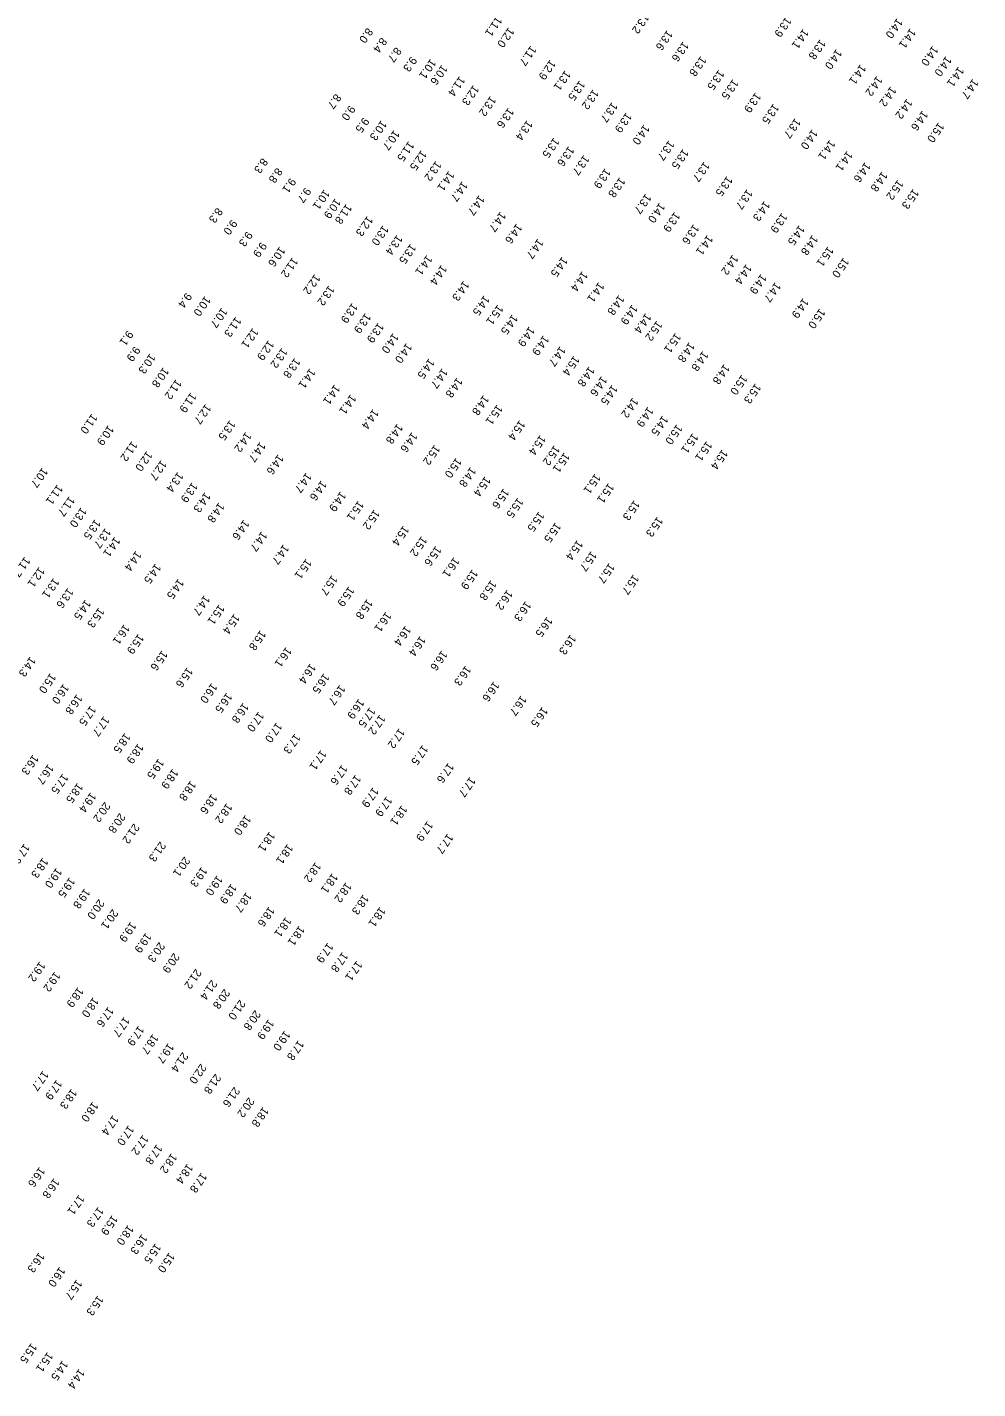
# Model space of a CAD drawing. Extents: x 815385 to 820851, y 582449 to 604245.
# Drawn here: x 817174 to 817768, y 584611 to 585462 of the extents above; entities that cross this region are included whole.
import ezdxf

# ---------------------------------------------------------------- set-up
doc = ezdxf.new("R2010")
doc.units = 0
doc.layers.add('V-TOPO-SOUN-021509', color=7, linetype='Continuous')
doc.layers.add('V-TOPO-SOUN-101408', color=7, linetype='Continuous')

msp = doc.modelspace()

# ---------------------------------------------------------------- texts
at = {"layer": 'V-TOPO-SOUN-021509'}
for s, p in [('13.9 ', (817647.89, 585468.39)), ('14.1 ', (817658.74, 585461.03)), ('14.0 ', (817717.43, 585467.62)), ('14.1 ', (817725.65, 585461.3)), ('13.8 ', (817669.26, 585454.39)), ('14.0 ', (817679.45, 585448.29)), ('14.0 ', (817739.62, 585450.38)), ('14.0 ', (817747.96, 585443.94)), ('14.1 ', (817694.46, 585438.8)), ('14.1 ', (817755.74, 585437.32)), ('14.2 ', (817704.76, 585431.54)), ('14.7 ', (817764.78, 585429.81)), ('14.2 ', (817713.42, 585425.04)), ('14.2 ', (817723.51, 585417.31)), ('14.6 ', (817733.27, 585409.94)), ('15.0 ', (817743.37, 585402.56))]:
    msp.add_text(s, height=5, rotation=234.911, dxfattribs=at).set_placement(p)
at = {"layer": 'V-TOPO-SOUN-101408'}
for s, p in [('11.1 ', (817467.09, 585468.75)), ('13.2 ', (817558.89, 585470.52)), ('8.0', (817386.22, 585461.66)), ('12.0 ', (817474.61, 585461.92)), ('13.6 ', (817573.71, 585460.17)), ('8.4', (817394.98, 585455.6)), ('13.6 ', (817583.69, 585453.06)), ('8.7', (817404.07, 585449.57)), ('9.3', (817413.72, 585443.74)), ('11.7 ', (817488.44, 585450.47)), ('13.8 ', (817594.69, 585443.92)), ('10.1 ', (817425.81, 585442.21)), ('10.6 ', (817432.9, 585438.55)), ('12.9 ', (817500.54, 585441.67)), ('13.1 ', (817509.9, 585435.01)), ('13.5 ', (817605.9, 585435.35)), ('11.4 ', (817443.93, 585431.4)), ('12.3 ', (817452.6, 585425.82)), ('13.5 ', (817518.93, 585428.7)), ('13.5 ', (817614.78, 585429.54)), ('8.7', (817366.39, 585420.47)), ('13.2 ', (817463.24, 585418.98)), ('13.2 ', (817527.45, 585423.19)), ('13.9 ', (817628.91, 585421.18)), ('9.0', (817375.21, 585413.29)), ('13.6 ', (817474.41, 585411.64)), ('13.7 ', (817539.21, 585415.12)), ('13.5 ', (817640.12, 585414.21)), ('9.5', (817383.89, 585405.67)), ('10.3 ', (817395.01, 585403.85)), ('13.4 ', (817486.11, 585403.89)), ('13.9 ', (817548.13, 585408.69)), ('14.0 ', (817559.21, 585401.14)), ('13.7 ', (817653.7, 585405.17)), ('10.7 ', (817402.98, 585397.75)), ('13.5 ', (817502.84, 585392.98)), ('14.0 ', (817664.37, 585398.23)), ('11.5 ', (817412.1, 585390.73)), ('12.5 ', (817420, 585385.11)), ('13.6 ', (817512.12, 585387.62)), ('13.7 ', (817574.72, 585391.31)), ('13.5 ', (817583.63, 585385.96)), ('14.1 ', (817675.29, 585391.64)), ('14.1 ', (817686.17, 585384.68)), ('8.3', (817320.57, 585380.34)), ('13.2 ', (817429.12, 585378.47)), ('13.7 ', (817521.59, 585382.11)), ('13.7 ', (817596.8, 585377.98)), ('14.6 ', (817697.42, 585377.68)), ('8.8', (817329.68, 585374.22)), ('9.1', (817338.15, 585367.91)), ('14.1 ', (817437.2, 585372.19)), ('13.9 ', (817534.92, 585373.86)), ('13.8 ', (817544.02, 585368.2)), ('13.5 ', (817611.1, 585368.98)), ('14.8 ', (817708, 585371.83)), ('15.2 ', (817717.86, 585366.7)), ('9.7', (817347.55, 585361.91)), ('10.1 ', (817359.33, 585360.6)), ('14.7 ', (817445.58, 585365.68)), ('13.7 ', (817560.25, 585357.96)), ('13.7 ', (817623.63, 585360.75)), ('15.3 ', (817727.54, 585361.02)), ('10.9 ', (817366.24, 585355.06)), ('11.8 ', (817373.17, 585351.6)), ('14.7 ', (817456.13, 585357.03)), ('14.0 ', (817568.91, 585352.33)), ('14.3 ', (817634.46, 585353.43)), ('8.3', (817292.28, 585349.31)), ('9.0', (817301.4, 585341.82)), ('12.3 ', (817386.31, 585344.05)), ('14.7 ', (817469.41, 585346.73)), ('13.9 ', (817578.34, 585346.61)), ('13.9 ', (817645.39, 585346.03)), ('9.3', (817310.99, 585334.51)), ('13.0 ', (817396.09, 585338.22)), ('13.4 ', (817404.85, 585332.24)), ('14.6 ', (817479.59, 585339.35)), ('13.6 ', (817590.22, 585338.89)), ('14.1 ', (817598.83, 585332.19)), ('14.5 ', (817656.27, 585338.37)), ('9.9', (817319.85, 585327.81)), ('10.6 ', (817331.48, 585324.94)), ('13.5 ', (817413.3, 585326.74)), ('14.7 ', (817492.84, 585329.89)), ('14.8 ', (817664.48, 585332.13)), ('15.1 ', (817674.21, 585325.04)), ('11.2 ', (817339.52, 585318.22)), ('14.1 ', (817423.45, 585319.63)), ('14.5 ', (817508.04, 585318.56)), ('14.2 ', (817614.64, 585319.86)), ('15.0 ', (817683.93, 585318.07)), ('12.2 ', (817353.38, 585307.72)), ('14.4 ', (817432.59, 585313.52)), ('14.4 ', (817520.64, 585309.57)), ('14.4 ', (817623.12, 585313.99)), ('14.9 ', (817632.4, 585307.87)), ('13.2 ', (817362.26, 585300.69)), ('14.3 ', (817446.47, 585303.59)), ('14.1 ', (817530.91, 585302.71)), ('14.7 ', (817641.28, 585302.74)), ('9.4', (817273.05, 585296.22)), ('10.0 ', (817284.86, 585294.08)), ('13.9 ', (817376.86, 585289.72)), ('14.5 ', (817459.27, 585294.46)), ('14.8 ', (817543.51, 585294.7)), ('14.9 ', (817658.69, 585292.77)), ('10.7 ', (817295.31, 585286.78)), ('13.9 ', (817385.04, 585283.36)), ('15.1 ', (817467.77, 585288.61)), ('14.5 ', (817476.89, 585282.58)), ('14.9 ', (817551.78, 585288.71)), ('14.4 ', (817560.25, 585283.32)), ('15.0 ', (817669.01, 585286.28)), ('11.3 ', (817304.02, 585281.05)), ('12.1 ', (817314.7, 585274.09)), ('13.9 ', (817393.14, 585277.42)), ('14.9 ', (817487.48, 585275.01)), ('15.2 ', (817567.2, 585278.62)), ('9.1', (817236.43, 585272.58)), ('12.9 ', (817324.5, 585266.45)), ('14.0 ', (817402.4, 585270.88)), ('14.0 ', (817410.76, 585264.69)), ('14.9 ', (817496.38, 585269.53)), ('15.1 ', (817578.91, 585271.01)), ('14.8 ', (817587.5, 585265.21)), ('9.9', (817240.81, 585262.73)), ('10.3 ', (817250.4, 585258.1)), ('13.2 ', (817332.9, 585261.65)), ('14.7 ', (817506.77, 585262.71)), ('15.4 ', (817515.44, 585256.81)), ('14.8 ', (817595.99, 585259.72)), ('10.8 ', (817258.78, 585249.5)), ('13.8 ', (817340.89, 585255.37)), ('14.1 ', (817350.36, 585248.88)), ('14.5 ', (817424.79, 585255.03)), ('14.7 ', (817433.1, 585248.9)), ('14.8 ', (817524.88, 585250.04)), ('14.8 ', (817609.32, 585251.51)), ('11.2 ', (817266.74, 585242.04)), ('14.1 ', (817365.79, 585238.75)), ('14.8 ', (817442.36, 585243.15)), ('14.6 ', (817532.71, 585244.02)), ('15.0 ', (817620.31, 585244.89)), ('15.3 ', (817628.85, 585239.45)), ('11.9 ', (817275.98, 585233.78)), ('14.1 ', (817375.84, 585232.67)), ('14.8 ', (817458.89, 585232.16)), ('14.5 ', (817539.3, 585238.62)), ('14.2 ', (817552.16, 585230.58)), ('12.7 ', (817285.19, 585226.6)), ('14.4 ', (817389.88, 585223.49)), ('15.1 ', (817467.4, 585226.2)), ('14.9 ', (817561.64, 585224.8)), ('11.0 ', (817214.12, 585220.56)), ('10.9 ', (817224.38, 585213.34)), ('13.5 ', (817300.35, 585216.51)), ('14.8 ', (817405.05, 585214.27)), ('15.4 ', (817481.47, 585216.5)), ('14.5 ', (817570.86, 585219.39)), ('15.0 ', (817579.72, 585213.9)), ('14.2 ', (817310.32, 585209.13)), ('14.6 ', (817414.14, 585208.98)), ('15.4 ', (817494.36, 585207.27)), ('15.1 ', (817589.63, 585208.34)), ('11.2 ', (817239.14, 585203.42)), ('12.0 ', (817248.44, 585197.2)), ('14.7 ', (817319.2, 585202.89)), ('15.2 ', (817428.29, 585201.09)), ('15.2 ', (817503.14, 585200.8)), ('15.1 ', (817509.35, 585196.29)), ('15.1 ', (817598.36, 585203.46)), ('15.4 ', (817608.15, 585198.24)), ('12.7 ', (817257.39, 585191.5)), ('14.6 ', (817330.48, 585195.12)), ('15.0 ', (817441.82, 585193.02)), ('10.7 ', (817183.13, 585186.92)), ('13.4 ', (817267.8, 585184.1)), ('14.7 ', (817348.03, 585183.71)), ('14.8 ', (817450.8, 585187.27)), ('15.4 ', (817459.84, 585181.4)), ('15.1 ', (817528.64, 585183.09)), ('11.1 ', (817192.5, 585176.26)), ('13.9 ', (817276.79, 585177.65)), ('14.3 ', (817284.82, 585171.44)), ('14.6 ', (817357.47, 585178.83)), ('14.9 ', (817369.5, 585171.96)), ('15.6 ', (817471.45, 585173.83)), ('15.1 ', (817537.04, 585177.18)), ('11.7 ', (817199.99, 585168.95)), ('14.8 ', (817293.48, 585165.08)), ('15.1 ', (817380.63, 585166.24)), ('15.5 ', (817480.31, 585168.05)), ('15.3 ', (817553.1, 585166.52)), ('13.0 ', (817207.41, 585162.07)), ('13.5 ', (817216.1, 585154.58)), ('14.6 ', (817309.03, 585154.3)), ('15.2 ', (817390.59, 585160.7)), ('15.5 ', (817493.51, 585159.46)), ('15.3 ', (817567.58, 585156.21)), ('13.7 ', (817222.5, 585149.07)), ('14.7 ', (817320.21, 585147.08)), ('15.4 ', (817408.87, 585150.66)), ('15.5 ', (817503.89, 585152.63)), ('14.1 ', (817228.37, 585143.62)), ('14.7 ', (817333.85, 585138.91)), ('15.2 ', (817420.16, 585144.02)), ('15.6 ', (817429.09, 585137.94)), ('15.4 ', (817517.53, 585141.6)), ('11.7 ', (817172.12, 585131.14)), ('14.4 ', (817241.63, 585134.83)), ('15.1 ', (817348.01, 585129.89)), ('16.1 ', (817440.41, 585130.87)), ('15.7 ', (817526.22, 585134.66)), ('12.1 ', (817181.11, 585124.75)), ('14.5 ', (817253.83, 585126.92)), ('15.7 ', (817364.14, 585119.66)), ('15.9 ', (817451.9, 585123.3)), ('15.7 ', (817537.44, 585127.21)), ('15.7 ', (817552.6, 585120.13)), ('13.1 ', (817190.22, 585117.91)), ('13.6 ', (817199.11, 585111.68)), ('14.5 ', (817268.14, 585117.43)), ('15.9 ', (817374.68, 585112.65)), ('15.8 ', (817463.51, 585116.53)), ('14.5 ', (817210.02, 585104.36)), ('14.7 ', (817284.42, 585107.14)), ('15.8 ', (817386.17, 585104.74)), ('16.2 ', (817473.7, 585110.49)), ('16.3 ', (817485.21, 585103.46)), ('15.3 ', (817218.41, 585099.47)), ('15.1 ', (817293.59, 585101.35)), ('15.4 ', (817303.1, 585095.48)), ('16.1 ', (817397.87, 585096.76)), ('16.1 ', (817234.31, 585088.97)), ('16.4 ', (817410.11, 585088.09)), ('16.5 ', (817498.57, 585093.65)), ('15.9 ', (817243.13, 585082.97)), ('15.8 ', (817319.42, 585085.27)), ('16.4 ', (817419.34, 585081.66)), ('16.3 ', (817513.27, 585082.63)), ('14.3 ', (817175.55, 585068.8)), ('15.6 ', (817257.95, 585072.63)), ('16.1 ', (817335.53, 585074.78)), ('16.6 ', (817432.82, 585072.63)), ('15.6 ', (817273.75, 585062.09)), ('16.4 ', (817350.63, 585064.51)), ('16.3 ', (817447.68, 585063.2)), ('15.0 ', (817188.18, 585058.45)), ('16.0 ', (817196.34, 585051.78)), ('16.0 ', (817288.98, 585052.29)), ('16.5 ', (817359.12, 585058.32)), ('16.6 ', (817465.34, 585053.31)), ('16.8 ', (817204.69, 585045.28)), ('16.5 ', (817298.34, 585046.24)), ('16.7 ', (817369.03, 585051.14)), ('16.7 ', (817482.37, 585044.45)), ('17.5 ', (817213.27, 585038.19)), ('16.8 ', (817308.7, 585039.91)), ('16.9 ', (817380.88, 585042.41)), ('17.5 ', (817387.83, 585037.18)), ('16.5 ', (817495.65, 585037.38)), ('17.7 ', (817221.59, 585031.58)), ('17.0 ', (817318.29, 585034.42)), ('17.0 ', (817329.53, 585027.69)), ('17.2 ', (817394.09, 585032.59)), ('18.5 ', (817234.75, 585021.09)), ('17.3 ', (817341.01, 585020.69)), ('17.2 ', (817406.21, 585024.04)), ('18.9 ', (817242.96, 585014.48)), ('17.1 ', (817357.26, 585010.45)), ('17.5 ', (817420.83, 585013.61)), ('16.3 ', (817177.32, 585007.54)), ('16.7 ', (817186.79, 585001.62)), ('19.5 ', (817255.72, 585005.02)), ('17.6 ', (817370.41, 585001.27)), ('17.6 ', (817436.9, 585002.46)), ('17.5 ', (817195.85, 584995.66)), ('18.9 ', (817264.62, 584998.74)), ('17.8 ', (817378.88, 584995.01)), ('17.7 ', (817450.45, 584993.65)), ('18.5 ', (817205.12, 584989.89)), ('19.4 ', (817213.32, 584983.99)), ('18.8 ', (817275.79, 584991.28)), ('17.9 ', (817389.86, 584987.14)), ('20.2 ', (817222.12, 584977.98)), ('18.6 ', (817288.98, 584983.06)), ('18.2 ', (817298.38, 584977.22)), ('17.9 ', (817398.35, 584981.5)), ('18.1 ', (817407.79, 584975.94)), ('20.8 ', (817231.56, 584971.13)), ('18.0 ', (817310.09, 584969.82)), ('21.2 ', (817240.39, 584964.55)), ('18.1 ', (817325.17, 584959.48)), ('17.9 ', (817423.86, 584966.03)), ('17.7 ', (817436.49, 584958.26)), ('17.8 ', (817171.85, 584951.97)), ('21.3 ', (817256.84, 584953.3)), ('18.1 ', (817336.42, 584951.74)), ('18.3 ', (817183.37, 584943.12)), ('20.1 ', (817271.99, 584943.89)), ('19.0 ', (817191.92, 584936.83)), ('19.3 ', (817282.72, 584937.48)), ('18.2 ', (817353.85, 584940.34)), ('18.1 ', (817364.39, 584933.52)), ('19.5 ', (817200.15, 584930.89)), ('19.8 ', (817209.57, 584923.98)), ('19.0 ', (817292.41, 584932.11)), ('18.9 ', (817301.17, 584926.92)), ('18.2 ', (817372.92, 584927.8)), ('20.0 ', (817218.44, 584917.28)), ('18.7 ', (817310.57, 584921.59)), ('18.3 ', (817383.75, 584920.2)), ('20.1 ', (817227.05, 584911.1)), ('18.6 ', (817324.88, 584912.64)), ('18.1 ', (817394.16, 584912.44)), ('19.9 ', (817238.35, 584903.08)), ('18.1 ', (817335.3, 584906.14)), ('18.1 ', (817343.71, 584900.71)), ('19.9 ', (817247.87, 584896.3)), ('20.3 ', (817256.23, 584890.51)), ('17.9 ', (817361.53, 584890.06)), ('20.9 ', (817265.38, 584883.72)), ('17.8 ', (817370.73, 584884.26)), ('19.2 ', (817181.52, 584878.31)), ('21.2 ', (817279.11, 584873.8)), ('17.1 ', (817379.66, 584878.81)), ('19.2 ', (817190.92, 584872.02)), ('21.4 ', (817288.94, 584866.9)), ('18.9 ', (817205.41, 584862.27)), ('18.0 ', (817214.94, 584856)), ('20.8 ', (817296.91, 584861.26)), ('17.6 ', (817224.28, 584850.01)), ('21.0 ', (817306.58, 584854.48)), ('20.8 ', (817316.14, 584847.97)), ('17.7 ', (817234.36, 584843.83)), ('19.9 ', (817324.52, 584842.25)), ('17.9 ', (817243.31, 584838.23)), ('18.7 ', (817252.22, 584833.04)), ('19.0 ', (817334.6, 584835.16)), ('19.7 ', (817261.89, 584827.34)), ('21.4 ', (817270.85, 584821.76)), ('17.8 ', (817343.17, 584829.14)), ('22.0 ', (817282.2, 584814.53)), ('17.7 ', (817183.54, 584810.12)), ('21.8 ', (817291.34, 584808.2)), ('17.9 ', (817192.05, 584804.49)), ('18.3 ', (817201.32, 584798.82)), ('21.6 ', (817303.14, 584800.04)), ('18.0 ', (817214.62, 584790.72)), ('20.2 ', (817312.17, 584793.51)), ('17.4 ', (817227.29, 584782.34)), ('18.8 ', (817321.14, 584787.51)), ('17.0 ', (817237.03, 584775.95)), ('17.2 ', (817246.01, 584770)), ('17.8 ', (817254.66, 584764.1)), ('18.2 ', (817263.85, 584758.57)), ('16.6 ', (817181.36, 584749.98)), ('18.4 ', (817273.85, 584752.03)), ('17.8 ', (817282.54, 584746.43)), ('16.8 ', (817190.4, 584742.93)), ('17.1 ', (817206.02, 584732.6)), ('17.3 ', (817218.06, 584724.99)), ('15.9 ', (817226.85, 584719.92)), ('18.0 ', (817236.74, 584713.72)), ('16.3 ', (817245.34, 584708.04)), ('16.3 ', (817181.04, 584696.61)), ('15.5 ', (817253.85, 584702.28)), ('15.0 ', (817262.45, 584696.55)), ('16.0 ', (817193.98, 584687.6)), ('15.7 ', (817204.59, 584679.67)), ('15.3 ', (817217.89, 584669.73)), ('15.5 ', (817176.29, 584639.97)), ('15.1 ', (817186.4, 584634.36)), ('14.5 ', (817195.76, 584629.16)), ('14.4 ', (817206.16, 584623.94))]:
    msp.add_text(s, height=5, rotation=234.911, dxfattribs=at).set_placement(p)

doc.saveas('drawing.dxf')
